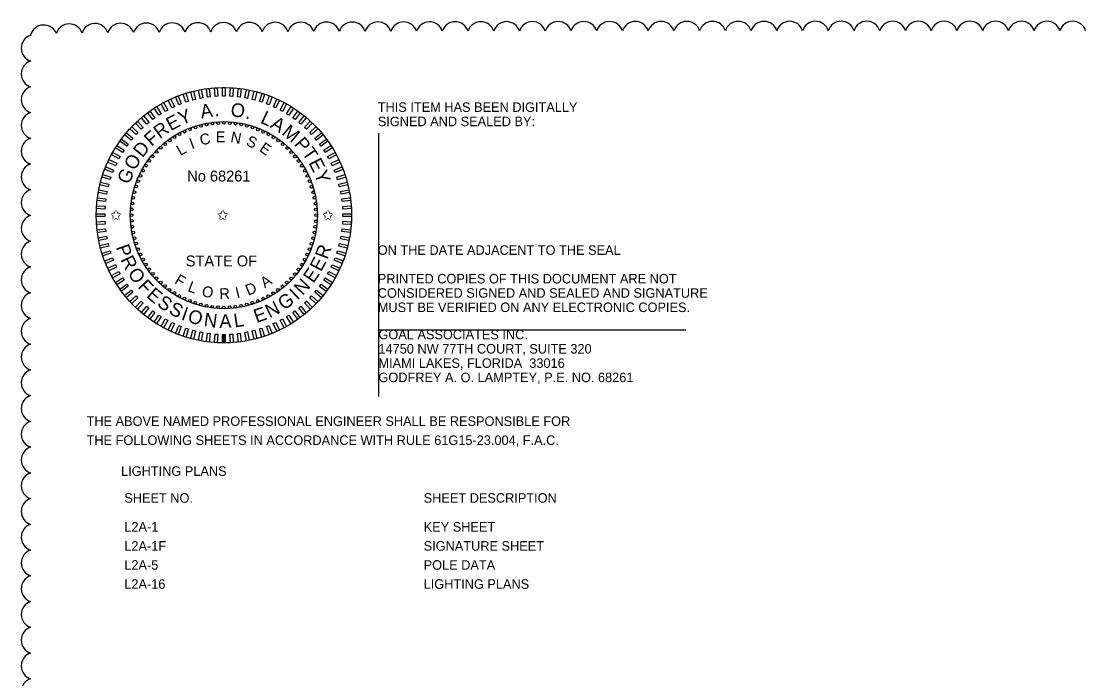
# Model space of a CAD drawing. Extents: x -811 to 10319, y -2309 to 9962.
# Drawn here: x -810.98 to -803.18, y -2265.38 to -2260.55 of the extents above; entities that cross this region are included whole.
import ezdxf

# ---------------------------------------------------------------- set-up
doc = ezdxf.new("R2010")
doc.units = 0
for name, color, linetype in [('AdhocPoint_dp', 7, 'Continuous'), ('PlotBorder_dp', 7, 'Continuous'), ('ScratchEle_dp', 7, 'Continuous'), ('TextMinor', 7, 'Continuous'), ('TextMisc', 7, 'Continuous'), ('TextShtNo', 7, 'Continuous')]:
    doc.layers.add(name, color=color, linetype=linetype)

msp = doc.modelspace()

# ---------------------------------------------------------------- linework, layer by layer
at = {"layer": 'AdhocPoint_dp'}
for p, q in [((-808.3546, -2261.3703), (-808.3546, -2263.305)), ((-808.3546, -2262.815), (-806.0979, -2262.815))]:
    msp.add_line(p, q, dxfattribs=at)
at = {"layer": 'ScratchEle_dp'}
for centre, radius, start, end in [((-810.8128, -2260.6762), 0.0992, 21.52097, 166.52097), ((-810.6255, -2260.6681), 0.0991, 18.44241, 163.44241), ((-810.4367, -2260.6654), 0.0991, 18.17187, 163.17187), ((-810.2478, -2260.6635), 0.0991, 18.03188, 163.03188), ((-810.0588, -2260.6618), 0.0991, 17.94243, 162.94243), ((-809.8699, -2260.6605), 0.0991, 17.8789, 162.8789), ((-809.6809, -2260.6593), 0.0991, 17.83076, 162.83076), ((-809.4919, -2260.6583), 0.0991, 17.79266, 162.79266), ((-809.3029, -2260.6574), 0.0991, 17.76151, 162.76151), ((-809.1139, -2260.6566), 0.0991, 17.73544, 162.73544), ((-808.9249, -2260.6558), 0.0991, 17.7132, 162.7132), ((-808.736, -2260.6551), 0.0991, 17.69393, 162.69393), ((-808.547, -2260.6545), 0.0991, 17.67702, 162.67702), ((-808.358, -2260.654), 0.0991, 17.66204, 162.66204), ((-808.169, -2260.6535), 0.0991, 17.64863, 162.64863), ((-807.98, -2260.653), 0.0991, 17.63655, 162.63655), ((-807.791, -2260.6526), 0.0991, 17.62558, 162.62558), ((-807.602, -2260.6522), 0.0991, 17.61556, 162.61556), ((-807.413, -2260.6518), 0.0991, 17.60637, 162.60637), ((-807.224, -2260.6515), 0.0991, 17.5979, 162.5979), ((-807.035, -2260.6512), 0.0991, 17.59006, 162.59006), ((-806.846, -2260.6509), 0.0991, 17.58277, 162.58277), ((-806.657, -2260.6506), 0.0991, 17.57597, 162.57597), ((-806.468, -2260.6504), 0.0991, 17.56961, 162.56961), ((-806.279, -2260.6501), 0.0991, 17.56364, 162.56364), ((-806.09, -2260.6499), 0.0991, 17.55803, 162.55803), ((-805.901, -2260.6498), 0.0991, 17.55274, 162.55274), ((-805.712, -2260.6496), 0.0991, 17.54774, 162.54774), ((-805.523, -2260.6494), 0.0991, 17.54301, 162.54301), ((-805.334, -2260.6493), 0.0991, 17.53852, 162.53852), ((-805.145, -2260.6492), 0.0991, 17.53425, 162.53425), ((-804.956, -2260.6491), 0.0991, 17.53018, 162.53018), ((-804.767, -2260.649), 0.0991, 17.52631, 162.52631), ((-804.578, -2260.6489), 0.0991, 17.52261, 162.52261), ((-804.389, -2260.6488), 0.0991, 17.51907, 162.51907), ((-804.2, -2260.6488), 0.0991, 17.51569, 162.51569), ((-804.011, -2260.6487), 0.0991, 17.51244, 162.51244), ((-803.822, -2260.6487), 0.0991, 17.50933, 162.50933), ((-803.633, -2260.6487), 0.0991, 17.50633, 162.50633), ((-803.444, -2260.6487), 0.0991, 17.50345, 162.50345), ((-803.2551, -2260.6487), 0.0991, 17.50077, 162.50077), ((-810.8794, -2260.7476), 0.099, 107.5, 252.5), ((-810.8794, -2260.9365), 0.0991, 107.5, 252.5), ((-810.8794, -2261.1255), 0.0991, 107.5, 252.5), ((-810.8794, -2261.3145), 0.0991, 107.5, 252.5), ((-810.8794, -2261.5035), 0.0991, 107.5, 252.5), ((-810.8794, -2261.6925), 0.0991, 107.5, 252.5), ((-810.8794, -2261.8815), 0.0991, 107.5, 252.5), ((-810.8794, -2262.0705), 0.0991, 107.5, 252.5), ((-810.8794, -2262.2595), 0.0991, 107.5, 252.5), ((-810.8794, -2262.4485), 0.0991, 107.5, 252.5), ((-810.8794, -2262.6375), 0.0991, 107.5, 252.5), ((-810.8794, -2262.8265), 0.0991, 107.5, 252.5), ((-810.8794, -2263.0155), 0.0991, 107.5, 252.5), ((-810.8794, -2263.2045), 0.0991, 107.5, 252.5), ((-810.8794, -2263.3935), 0.0991, 107.5, 252.5), ((-810.8794, -2263.5825), 0.0991, 107.5, 252.5), ((-810.8794, -2263.7715), 0.0991, 107.5, 252.5), ((-810.8794, -2263.9605), 0.0991, 107.5, 252.5), ((-810.8794, -2264.1495), 0.0991, 107.5, 252.5), ((-810.8794, -2264.3385), 0.0991, 107.5, 252.5), ((-810.8794, -2264.5275), 0.0991, 107.5, 252.5), ((-810.8794, -2264.7165), 0.0991, 107.5, 252.5), ((-810.8794, -2264.9055), 0.0991, 107.5, 252.5), ((-810.8794, -2265.0945), 0.0991, 107.5, 252.5), ((-810.8794, -2265.2835), 0.0991, 107.50047, 252.50047), ((-810.8794, -2265.4725), 0.0991, 107.52584, 252.52584)]:
    msp.add_arc(centre, radius, start, end, dxfattribs=at)
at = {"layer": 'TextMinor'}
for radius in [0.9375, 0.6875]:
    msp.add_circle((-809.4901, -2261.9737), radius, dxfattribs=at)
at = {"layer": 'TextShtNo'}
for p, q in [((-809.5001, -2262.9113), (-809.5003, -2262.8488)), ((-809.4901, -2262.9112), (-809.4903, -2262.8487)), ((-809.4801, -2262.9112), (-809.4803, -2262.8487))]:
    msp.add_line(p, q, dxfattribs=at)
for points in [[(-809.7508, -2261.1384), (-809.77, -2261.1446), (-809.7893, -2261.0852), (-809.7701, -2261.079)], [(-809.6979, -2261.1237), (-809.7174, -2261.1287), (-809.7329, -2261.0682), (-809.7134, -2261.0632)], [(-809.6441, -2261.1123), (-809.6639, -2261.1161), (-809.6756, -2261.0547), (-809.6558, -2261.051)], [(-809.5897, -2261.1043), (-809.6097, -2261.1069), (-809.6175, -2261.0449), (-809.5975, -2261.0424)], [(-809.5349, -2261.0998), (-809.555, -2261.1011), (-809.559, -2261.0387), (-809.5388, -2261.0375)], [(-809.4799, -2261.0987), (-809.5001, -2261.0987), (-809.5001, -2261.0363), (-809.4799, -2261.0363)], [(-809.425, -2261.1011), (-809.4452, -2261.0998), (-809.4412, -2261.0375), (-809.4211, -2261.0387)], [(-809.3703, -2261.1069), (-809.3904, -2261.1043), (-809.3825, -2261.0424), (-809.3625, -2261.0449)], [(-809.3161, -2261.1161), (-809.336, -2261.1123), (-809.3243, -2261.051), (-809.3044, -2261.0548)], [(-809.2626, -2261.1287), (-809.2822, -2261.1237), (-809.2667, -2261.0632), (-809.2471, -2261.0682)], [(-809.21, -2261.1447), (-809.2292, -2261.1384), (-809.2099, -2261.0791), (-809.1907, -2261.0853)], [(-809.9027, -2261.202), (-809.9204, -2261.2118), (-809.9505, -2261.157), (-809.9328, -2261.1473)], [(-809.8535, -2261.1776), (-809.8717, -2261.1862), (-809.8983, -2261.1297), (-809.8801, -2261.1211)], [(-809.8028, -2261.1564), (-809.8215, -2261.1638), (-809.8445, -2261.1058), (-809.8258, -2261.0983)], [(-809.1585, -2261.1639), (-809.1773, -2261.1565), (-809.1543, -2261.0984), (-809.1355, -2261.1058)], [(-809.1083, -2261.1863), (-809.1266, -2261.1777), (-809.1, -2261.1212), (-809.0817, -2261.1298)], [(-809.0596, -2261.2118), (-809.0773, -2261.2021), (-809.0473, -2261.1474), (-809.0296, -2261.1571)], [(-810.04, -2261.293), (-810.0556, -2261.3059), (-810.0954, -2261.2578), (-810.0798, -2261.2449)], [(-809.9962, -2261.2598), (-810.0125, -2261.2717), (-810.0492, -2261.2212), (-810.0329, -2261.2093)], [(-809.9504, -2261.2295), (-809.9674, -2261.2403), (-810.0009, -2261.1876), (-809.9838, -2261.1767)], [(-809.0127, -2261.2404), (-809.0297, -2261.2296), (-808.9962, -2261.1768), (-808.9792, -2261.1877)], [(-808.9675, -2261.2718), (-808.9839, -2261.2599), (-808.9472, -2261.2094), (-808.9308, -2261.2213)], [(-808.9245, -2261.306), (-808.9401, -2261.2931), (-808.9003, -2261.245), (-808.8847, -2261.2579)], [(-810.121, -2261.3673), (-810.1348, -2261.382), (-810.1803, -2261.3393), (-810.1665, -2261.3246)], [(-810.0817, -2261.3289), (-810.0964, -2261.3427), (-810.1391, -2261.2972), (-810.1244, -2261.2834)], [(-808.8837, -2261.3428), (-808.8984, -2261.329), (-808.8557, -2261.2835), (-808.8409, -2261.2973)], [(-808.8453, -2261.3822), (-808.8591, -2261.3674), (-808.8136, -2261.3247), (-808.7998, -2261.3394)], [(-810.1578, -2261.4081), (-810.1707, -2261.4237), (-810.2188, -2261.3839), (-810.206, -2261.3683)], [(-808.8094, -2261.4238), (-808.8223, -2261.4083), (-808.7742, -2261.3685), (-808.7613, -2261.384)], [(-810.2235, -2261.4963), (-810.2343, -2261.5133), (-810.287, -2261.4798), (-810.2762, -2261.4628)], [(-810.192, -2261.4512), (-810.2039, -2261.4675), (-810.2544, -2261.4308), (-810.2426, -2261.4145)], [(-808.7762, -2261.4676), (-808.7881, -2261.4513), (-808.7376, -2261.4146), (-808.7257, -2261.4309)], [(-808.7458, -2261.5135), (-808.7567, -2261.4964), (-808.7039, -2261.463), (-808.6931, -2261.48)], [(-810.252, -2261.5433), (-810.2617, -2261.5609), (-810.3164, -2261.5309), (-810.3067, -2261.5132)], [(-808.7184, -2261.5611), (-808.7281, -2261.5434), (-808.6734, -2261.5133), (-808.6637, -2261.531)], [(-810.3, -2261.6421), (-810.3074, -2261.6609), (-810.3654, -2261.6379), (-810.358, -2261.6192)], [(-810.2775, -2261.5919), (-810.2861, -2261.6102), (-810.3426, -2261.5836), (-810.334, -2261.5654)], [(-808.694, -2261.6104), (-808.7026, -2261.5921), (-808.6461, -2261.5655), (-808.6375, -2261.5838)], [(-808.6728, -2261.6611), (-808.6802, -2261.6423), (-808.6222, -2261.6193), (-808.6147, -2261.6381)], [(-810.3192, -2261.6936), (-810.3254, -2261.7128), (-810.3848, -2261.6935), (-810.3786, -2261.6743)], [(-808.6548, -2261.713), (-808.661, -2261.6938), (-808.6016, -2261.6745), (-808.5954, -2261.6937)], [(-810.3477, -2261.7998), (-810.3515, -2261.8196), (-810.4129, -2261.8079), (-810.4091, -2261.7881)], [(-810.3351, -2261.7463), (-810.3401, -2261.7658), (-810.4006, -2261.7503), (-810.3956, -2261.7307)], [(-808.64, -2261.766), (-808.6451, -2261.7464), (-808.5846, -2261.7309), (-808.5796, -2261.7505)], [(-808.6287, -2261.8198), (-808.6325, -2261.7999), (-808.5711, -2261.7882), (-808.5673, -2261.8081)], [(-810.357, -2261.854), (-810.3595, -2261.874), (-810.4214, -2261.8662), (-810.4189, -2261.8461)], [(-808.6207, -2261.8742), (-808.6232, -2261.8541), (-808.5613, -2261.8463), (-808.5588, -2261.8663)], [(-810.3628, -2261.9086), (-810.364, -2261.9288), (-810.4264, -2261.9248), (-810.4251, -2261.9047)], [(-808.6162, -2261.929), (-808.6174, -2261.9088), (-808.5551, -2261.9049), (-808.5539, -2261.925)], [(-810.3651, -2261.9635), (-810.3651, -2261.9837), (-810.4276, -2261.9837), (-810.4276, -2261.9635)], [(-810.3641, -2262.0185), (-810.3628, -2262.0387), (-810.4251, -2262.0426), (-810.4264, -2262.0224)], [(-808.6175, -2262.0388), (-808.6162, -2262.0187), (-808.5539, -2262.0226), (-808.5551, -2262.0428)], [(-808.6151, -2261.9839), (-808.6151, -2261.9637), (-808.5526, -2261.9637), (-808.5526, -2261.9839)], [(-810.3595, -2262.0733), (-810.357, -2262.0933), (-810.4189, -2262.1011), (-810.4215, -2262.0811)], [(-808.6233, -2262.0935), (-808.6207, -2262.0735), (-808.5588, -2262.0813), (-808.5613, -2262.1013)], [(-810.3516, -2262.1277), (-810.3478, -2262.1475), (-810.4091, -2262.1592), (-810.4129, -2262.1394)], [(-810.3402, -2262.1815), (-810.3352, -2262.201), (-810.3956, -2262.2166), (-810.4007, -2262.197)], [(-808.6451, -2262.2012), (-808.6401, -2262.1817), (-808.5796, -2262.1972), (-808.5846, -2262.2167)], [(-808.6325, -2262.1477), (-808.6287, -2262.1279), (-808.5674, -2262.1396), (-808.5712, -2262.1594)], [(-810.3255, -2262.2344), (-810.3192, -2262.2536), (-810.3786, -2262.2729), (-810.3849, -2262.2537)], [(-808.6611, -2262.2538), (-808.6548, -2262.2346), (-808.5954, -2262.2539), (-808.6017, -2262.2731)], [(-810.3074, -2262.2864), (-810.3, -2262.3051), (-810.3581, -2262.3281), (-810.3655, -2262.3094)], [(-810.2862, -2262.3371), (-810.2776, -2262.3553), (-810.3341, -2262.3819), (-810.3427, -2262.3637)], [(-808.7027, -2262.3555), (-808.6941, -2262.3372), (-808.6376, -2262.3638), (-808.6462, -2262.3821)], [(-808.6803, -2262.3053), (-808.6729, -2262.2866), (-808.6148, -2262.3095), (-808.6222, -2262.3283)], [(-810.2618, -2262.3864), (-810.2521, -2262.404), (-810.3068, -2262.4341), (-810.3165, -2262.4164)], [(-808.7282, -2262.4042), (-808.7185, -2262.3865), (-808.6638, -2262.4166), (-808.6735, -2262.4343)], [(-810.2344, -2262.434), (-810.2236, -2262.451), (-810.2763, -2262.4845), (-810.2871, -2262.4674)], [(-810.204, -2262.4798), (-810.1922, -2262.4961), (-810.2427, -2262.5328), (-810.2545, -2262.5165)], [(-808.7882, -2262.4963), (-808.7763, -2262.48), (-808.7258, -2262.5167), (-808.7377, -2262.533)], [(-808.7568, -2262.4512), (-808.7459, -2262.4341), (-808.6932, -2262.4676), (-808.704, -2262.4847)], [(-810.1708, -2262.5236), (-810.158, -2262.5392), (-810.2061, -2262.579), (-810.2189, -2262.5634)], [(-810.135, -2262.5653), (-810.1211, -2262.58), (-810.1667, -2262.6228), (-810.1805, -2262.608)], [(-808.8592, -2262.5802), (-808.8454, -2262.5654), (-808.7999, -2262.6082), (-808.8137, -2262.6229)], [(-808.8224, -2262.5393), (-808.8095, -2262.5238), (-808.7614, -2262.5636), (-808.7743, -2262.5791)], [(-810.0965, -2262.6046), (-810.0818, -2262.6184), (-810.1246, -2262.664), (-810.1393, -2262.6501)], [(-810.0557, -2262.6415), (-810.0402, -2262.6543), (-810.08, -2262.7024), (-810.0955, -2262.6896)], [(-808.9402, -2262.6544), (-808.9246, -2262.6416), (-808.8848, -2262.6897), (-808.9004, -2262.7026)], [(-808.8985, -2262.6186), (-808.8838, -2262.6048), (-808.8411, -2262.6503), (-808.8558, -2262.6641)], [(-810.0127, -2262.6757), (-809.9964, -2262.6875), (-810.0331, -2262.738), (-810.0494, -2262.7262)], [(-809.9676, -2262.7071), (-809.9505, -2262.7179), (-809.984, -2262.7706), (-810.001, -2262.7598)], [(-809.0299, -2262.718), (-809.0128, -2262.7072), (-808.9794, -2262.7599), (-808.9964, -2262.7707)], [(-808.984, -2262.6876), (-808.9677, -2262.6758), (-808.931, -2262.7263), (-808.9473, -2262.7381)], [(-809.9206, -2262.7356), (-809.9029, -2262.7453), (-809.933, -2262.8001), (-809.9507, -2262.7903)], [(-809.8719, -2262.7611), (-809.8536, -2262.7697), (-809.8802, -2262.8262), (-809.8985, -2262.8176)], [(-809.8217, -2262.7836), (-809.8029, -2262.791), (-809.8259, -2262.849), (-809.8447, -2262.8416)], [(-809.7702, -2262.8028), (-809.751, -2262.809), (-809.7703, -2262.8684), (-809.7895, -2262.8622)], [(-809.2294, -2262.8091), (-809.2102, -2262.8028), (-809.1909, -2262.8622), (-809.2101, -2262.8685)], [(-809.1775, -2262.7911), (-809.1587, -2262.7836), (-809.1357, -2262.8417), (-809.1545, -2262.8491)], [(-809.1268, -2262.7698), (-809.1085, -2262.7612), (-809.0819, -2262.8177), (-809.1002, -2262.8263)], [(-809.0775, -2262.7454), (-809.0598, -2262.7357), (-809.0297, -2262.7904), (-809.0474, -2262.8001)], [(-809.7176, -2262.8187), (-809.698, -2262.8238), (-809.7136, -2262.8842), (-809.7331, -2262.8792)], [(-809.6641, -2262.8314), (-809.6443, -2262.8351), (-809.656, -2262.8965), (-809.6758, -2262.8927)], [(-809.6099, -2262.8406), (-809.5899, -2262.8431), (-809.5977, -2262.9051), (-809.6177, -2262.9025)], [(-809.5552, -2262.8464), (-809.5351, -2262.8477), (-809.539, -2262.91), (-809.5591, -2262.9087)], [(-809.5003, -2262.8488), (-809.4801, -2262.8488), (-809.4801, -2262.9112), (-809.5003, -2262.9112)], [(-809.4453, -2262.8477), (-809.4252, -2262.8464), (-809.4213, -2262.9087), (-809.4414, -2262.91)], [(-809.3906, -2262.8431), (-809.3705, -2262.8406), (-809.3627, -2262.9026), (-809.3827, -2262.9051)], [(-809.3362, -2262.8352), (-809.3163, -2262.8314), (-809.3046, -2262.8927), (-809.3245, -2262.8965)], [(-809.2824, -2262.8238), (-809.2628, -2262.8188), (-809.2473, -2262.8793), (-809.2668, -2262.8843)]]:
    msp.add_lwpolyline(points, close=True, dxfattribs=at)
for centre in [(-809.6989, -2261.3292), (-809.6581, -2261.3174), (-809.6165, -2261.3082), (-809.5745, -2261.3015), (-809.5321, -2261.2976), (-809.4896, -2261.2963), (-809.447, -2261.2976), (-809.4046, -2261.3017), (-809.3626, -2261.3084), (-809.3211, -2261.3177), (-809.2802, -2261.3296), (-809.8526, -2261.4014), (-809.816, -2261.3798), (-809.7781, -2261.3605), (-809.739, -2261.3436), (-809.2402, -2261.344), (-809.2012, -2261.361), (-809.1633, -2261.3803), (-809.1266, -2261.402), (-809.9535, -2261.4795), (-809.9215, -2261.4514), (-809.8879, -2261.4253), (-809.0915, -2261.426), (-809.0578, -2261.4521), (-809.0259, -2261.4803), (-810.0118, -2261.5415), (-809.9836, -2261.5096), (-808.9959, -2261.5104), (-808.9678, -2261.5423), (-810.0835, -2261.6469), (-810.0618, -2261.6102), (-810.0379, -2261.5751), (-808.9417, -2261.576), (-808.9178, -2261.6112), (-810.1198, -2261.7238), (-810.1029, -2261.6848), (-808.8962, -2261.6478), (-808.8769, -2261.6858), (-808.86, -2261.7249), (-810.1343, -2261.7638), (-808.8456, -2261.7649), (-810.1555, -2261.8462), (-810.1462, -2261.8047), (-808.8338, -2261.8058), (-808.8245, -2261.8473), (-810.1662, -2261.9306), (-810.1622, -2261.8883), (-808.8179, -2261.8894), (-808.814, -2261.9318), (-810.1676, -2261.9732), (-810.1663, -2262.0157), (-808.814, -2262.0168), (-808.8126, -2261.9743), (-810.1623, -2262.0581), (-810.1557, -2262.1001), (-808.8248, -2262.1012), (-808.8181, -2262.0592), (-810.1464, -2262.1417), (-810.1346, -2262.1825), (-808.846, -2262.1836), (-808.8341, -2262.1428), (-810.1202, -2262.2226), (-810.1033, -2262.2617), (-808.8774, -2262.2627), (-808.8604, -2262.2236), (-810.0841, -2262.2996), (-810.0624, -2262.3363), (-808.9184, -2262.3372), (-808.8967, -2262.3006), (-810.0385, -2262.3715), (-810.0125, -2262.4051), (-808.9685, -2262.406), (-808.9424, -2262.3724), (-809.9844, -2262.4371), (-809.9543, -2262.4672), (-809.9224, -2262.4954), (-809.0587, -2262.4961), (-809.0268, -2262.468), (-808.9967, -2262.4379), (-809.8888, -2262.5215), (-809.8536, -2262.5454), (-809.817, -2262.5671), (-809.1642, -2262.5677), (-809.1276, -2262.546), (-809.0924, -2262.5221), (-809.7791, -2262.5865), (-809.74, -2262.6034), (-809.7, -2262.6179), (-809.6591, -2262.6298), (-809.6176, -2262.6391), (-809.5756, -2262.6458), (-809.5332, -2262.6498), (-809.4901, -2262.6512), (-809.4481, -2262.6499), (-809.4058, -2262.6459), (-809.3637, -2262.6393), (-809.3222, -2262.6301), (-809.2813, -2262.6182), (-809.2412, -2262.6038), (-809.2022, -2262.587)]:
    msp.add_circle(centre, 0.01, dxfattribs=at)

# ---------------------------------------------------------------- texts
at = {"layer": 'PlotBorder_dp'}
for s, p in [('THIS ITEM HAS BEEN DIGITALLY', (-808.3596, -2261.2152)), ('SIGNED AND SEALED BY:', (-808.3596, -2261.3202)), ('ON THE DATE ADJACENT TO THE SEAL', (-808.3596, -2262.2652)), ('PRINTED COPIES OF THIS DOCUMENT ARE NOT ', (-808.3596, -2262.4752)), ('CONSIDERED SIGNED AND SEALED AND SIGNATURE ', (-808.3596, -2262.5802)), ('MUST BE VERIFIED ON ANY ELECTRONIC COPIES.', (-808.3596, -2262.6852)), ('GOAL ASSOCIATES INC.', (-808.3546, -2262.885)), ('14750 NW 77TH COURT, SUITE 320', (-808.3546, -2262.99)), ('MIAMI LAKES, FLORIDA  33016', (-808.3546, -2263.095)), ('GODFREY A. O. LAMPTEY, P.E. NO. 68261', (-808.3546, -2263.2)), ('THE ABOVE NAMED PROFESSIONAL ENGINEER SHALL BE RESPONSIBLE FOR ', (-810.4987, -2263.5212)), ('THE FOLLOWING SHEETS IN ACCORDANCE WITH RULE 61G15-23.004, F.A.C.', (-810.4987, -2263.6612)), ('LIGHTING PLANS', (-810.245, -2263.8882))]:
    msp.add_text(s, height=0.07, dxfattribs=at).set_placement(p)
at = {"layer": 'TextMisc'}
for s, p in [('SHEET NO.', (-810.2215, -2264.0852)), ('SHEET DESCRIPTION', (-808.0226, -2264.0852)), ('L2A-1', (-810.2215, -2264.2974)), ('KEY SHEET', (-808.0226, -2264.2974)), ('L2A-1F', (-810.2215, -2264.4374)), ('SIGNATURE SHEET', (-808.0226, -2264.4374)), ('L2A-5', (-810.2215, -2264.5774)), ('POLE DATA', (-808.0226, -2264.5774)), ('L2A-16', (-810.2215, -2264.7174)), ('LIGHTING PLANS', (-808.0226, -2264.7174))]:
    msp.add_text(s, height=0.07, dxfattribs=at).set_placement(p)
at = {"layer": 'TextShtNo'}
for s, height, rotation, p in [('A', 0.1, 8.80884, (-809.6551, -2261.2631)), ('O', 0.1, 352.18771, (-809.4449, -2261.2456)), ('E', 0.1, 28.10553, (-809.8806, -2261.3575)), ('Y', 0.1, 21.06329, (-809.8021, -2261.3143)), ('.', 0.1, 1.04184, (-809.5575, -2261.2473)), ('L', 0.1, 334.67271, (-809.2279, -2261.293)), ('R', 0.1, 35.92688, (-809.9609, -2261.4164)), ('.', 0.1, 343.52684, (-809.3358, -2261.2607)), ('A', 0.1, 328.40959, (-809.1552, -2261.3257)), ('M', 0.1, 320.6426, (-809.0707, -2261.3769)), ('F', 0.1, 42.37723, (-810.0205, -2261.4728)), ('C', 0.08, 12.20255, (-809.6579, -2261.4621)), ('E', 0.08, 0.41861, (-809.5498, -2261.4386)), ('N', 0.08, 349.29143, (-809.4455, -2261.4372)), ('S', 0.08, 337.02207, (-809.3325, -2261.4589)), ('P', 0.1, 311.19658, (-808.9784, -2261.4538)), ('D', 0.1, 50.8569, (-810.0885, -2261.5565)), ('L', 0.08, 30.40215, (-809.8093, -2261.5401)), ('I', 0.08, 20.01168, (-809.7258, -2261.4897)), ('E', 0.08, 325.86633, (-809.2358, -2261.4992)), ('T', 0.1, 304.45632, (-808.9209, -2261.5175)), ('O', 0.1, 59.51777, (-810.1446, -2261.6514)), ('E', 0.1, 297.63152, (-808.8707, -2261.5883)), ('Y', 0.1, 290.58928, (-808.8281, -2261.6672)), ('G', 0.1, 68.0518, (-810.1851, -2261.7521)), ('P', 0.1, 289.40551, (-810.2848, -2262.2083)), ('R', 0.1, 69.5134, (-808.7299, -2262.3034)), ('R', 0.1, 296.14576, (-810.2518, -2262.3)), ('E', 0.1, 62.47116, (-808.7761, -2262.3941)), ('O', 0.1, 303.96711, (-810.2003, -2262.4006)), ('F', 0.08, 328.72408, (-809.8582, -2262.4703)), ('E', 0.1, 55.42892, (-808.833, -2262.4785)), ('F', 0.1, 312.62798, (-810.1279, -2262.5027)), ('L', 0.08, 339.29159, (-809.7609, -2262.5294)), ('O', 0.08, 349.68206, (-809.6562, -2262.5691)), ('D', 0.08, 22.01279, (-809.312, -2262.5656)), ('A', 0.08, 34.49917, (-809.1883, -2262.5131)), ('N', 0.1, 47.17876, (-808.9123, -2262.5676)), ('E', 0.1, 319.07833, (-810.0645, -2262.571)), ('S', 0.1, 326.12056, (-809.9869, -2262.6369)), ('R', 0.08, 2.33977, (-809.5217, -2262.591)), ('I', 0.08, 14.20366, (-809.3941, -2262.5843)), ('G', 0.1, 35.11153, (-809.0492, -2262.6753)), ('I', 0.1, 43.64556, (-808.9499, -2262.6021)), ('S', 0.1, 333.193, (-809.9015, -2262.693)), ('I', 0.1, 340.26543, (-809.8098, -2262.7382)), ('E', 0.1, 19.81912, (-809.2498, -2262.7667)), ('N', 0.1, 26.86136, (-809.1544, -2262.7313)), ('O', 0.1, 343.79863, (-809.7621, -2262.7564)), ('N', 0.1, 352.45949, (-809.6411, -2262.7885)), ('A', 0.1, 0.70966, (-809.5227, -2262.8017)), ('L', 0.1, 8.47665, (-809.4105, -2262.7985))]:
    msp.add_text(s, height=height, rotation=rotation, dxfattribs=at).set_placement(p)
for s, p in [('No 68261', (-809.7591, -2261.7265)), ('✩', (-810.3251, -2262.0117)), ('✩', (-809.5404, -2262.0117)), ('✩', (-808.7685, -2262.0117)), ('STATE OF', (-809.7698, -2262.3499))]:
    msp.add_text(s, height=0.08, dxfattribs=at).set_placement(p)

doc.saveas('drawing.dxf')
